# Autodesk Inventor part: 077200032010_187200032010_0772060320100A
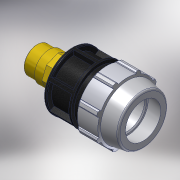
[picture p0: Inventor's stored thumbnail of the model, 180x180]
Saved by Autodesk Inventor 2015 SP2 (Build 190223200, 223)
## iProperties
Created: 2017-02
Part Number: 077200032010_187200032010_0772060320100A
Material: PVC-Piping
Description: PLASSON MALE ADAPTOR INTEGRAL BRASS THREAD 32-1"
Document SubType Name: Modeling
Designer: KIM
Mass: 92.6774 g
Surface Area: 199.44 cm^2
Volume: 66.1981 cm^3
Density: 1.4 g/cm^3
Appearance: PTFE
Author: KIM
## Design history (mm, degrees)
derived "07720.ipt"
feature "Solid1::07720.ipt"
tag "TaggingFeature1"
body "Solid1"
other parameters: "d2" = 32, "d4" = 20.14286, "d5" = 20.14286, "d7" = 64, "d8" = 48, "d9" = 20.14286, "d11" = 4.02857, "d12" = 51.2, "d13" = 120 deg, "d14" = 48, "d15" = 10 deg, "d16" = 57.6, "d18" = 1.6, "d19" = 35 deg, "d20" = 17.5 deg, "d21" = 59.52, "d23" = 0, "d25" = 360 deg, "d27" = 1.28, "d34" = 3.2, "d36" = 0, "d42" = 28.2, "d43" = 1.92, "d46" = 0.96, "d49" = 83, "d51" = 141, "d53" = 0.64, "d55" = 360 deg, "d59" = 28.2, "d60" = 33.249, "d61" = 36.5739, "d63" = 47, "d64" = 23.2743, "d65" = 141, "d66" = 15.04822, "d67" = 0, "d68" = 0.64, "d71" = 30 deg, "d72" = 29.9241, "d_" = 32, "E_" = 64, "H_" = 141, "l_" = 83, "R_" = 33.249, "d73" = 25.08037
